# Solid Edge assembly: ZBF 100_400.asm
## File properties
Title: Zylinder
Author: bmolnar
Template: iso metric assembly.asm
Last saved by: bmolnar
Revision: 34
Application: Solid Edge
Username: bmolnar
Dokumentum tartalom típus: 1
Document Number: ZBF 100/400
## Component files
Profilrohr.par
Kolbenstange.par
Mutter.par
Kit.par
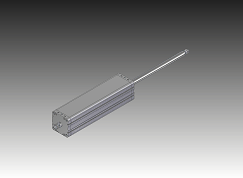
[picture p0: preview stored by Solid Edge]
